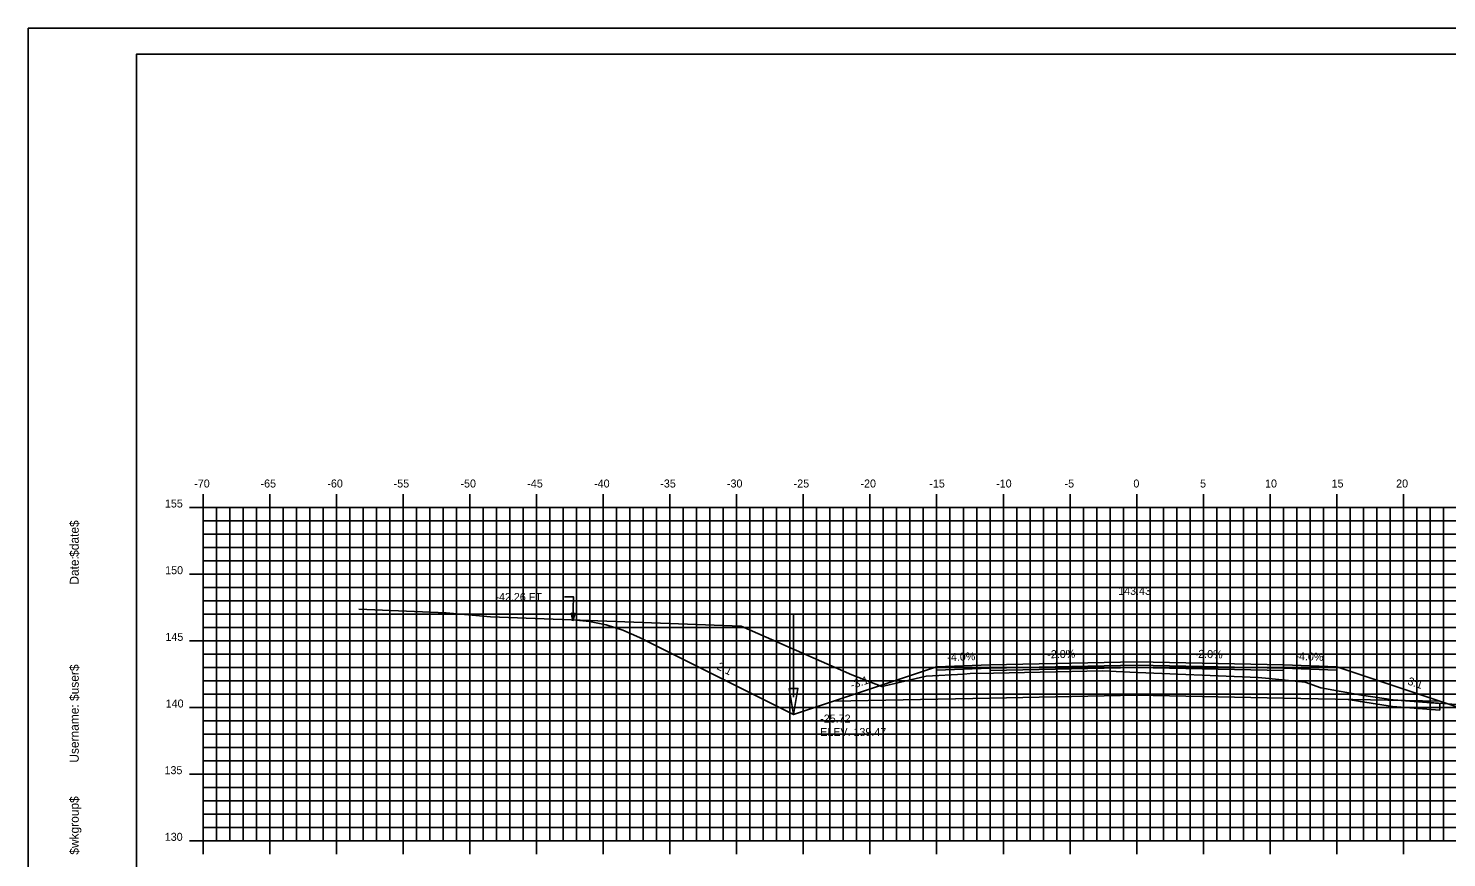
# Model space of a CAD drawing. Extents: x 1144307 to 1144477, y 608981 to 609091.
# Drawn here: x 1144307 to 1144413.3, y 609029.1 to 609091.3 of the extents above; entities that cross this region are included whole.
import ezdxf

# ---------------------------------------------------------------- set-up
doc = ezdxf.new("R2010")
doc.units = 0
for name, color, linetype in [('ANNOTATION', 7, 'Continuous'), ('BORDER', 7, 'Continuous'), ('D_Drainage_Ditch_Line', 7, 'Continuous'), ('D_Roadway_Centerline', 7, 'Continuous'), ('D_Roadway_Centerline_Text', 7, 'Continuous'), ('D_Roadway_Edge_Shoulder', 7, 'Continuous'), ('D_Roadway_Edge_TW', 7, 'Continuous'), ('D_Roadway_Pavement', 7, 'Continuous'), ('D_Roadway_SlopeLines', 7, 'Continuous'), ('D_Roadway_SubGrade', 7, 'Continuous'), ('D_Text_Standard', 7, 'Continuous'), ('H_V ANNOTATION', 7, 'Continuous'), ('MAJOR', 7, 'Continuous'), ('MINOR', 7, 'Continuous'), ('PLOT BOUNDARY', 7, 'Continuous'), ('S_Roadway_Centerline', 7, 'Continuous'), ('SHADING', 7, 'Continuous')]:
    doc.layers.add(name, color=color, linetype=linetype)

msp = doc.modelspace()

# ---------------------------------------------------------------- linework, layer by layer
msp.add_lwpolyline([(1144347.84, 609046.92), (1144349.09, 609046.8), (1144350.34, 609046.54), (1144351.59, 609046.13), (1144352.84, 609045.58), (1144364.38, 609039.81), (1144367.38, 609040.81), (1144375.1, 609043.38), (1144375.11, 609043.38), (1144379.11, 609043.54), (1144390.11, 609043.76), (1144401.11, 609043.54), (1144405.11, 609043.38), (1144412.83, 609040.81), (1144415.83, 609039.81), (1144416.37, 609040.04), (1144416.91, 609040.2), (1144417.45, 609040.29), (1144418, 609040.31)])
at = {"layer": 'BORDER'}
msp.add_lwpolyline([(1144315.11, 608984.34), (1144475.11, 608984.34), (1144475.11, 609089.34), (1144315.11, 609089.34)], close=True, dxfattribs=at)
at = {"layer": 'D_Drainage_Ditch_Line'}
msp.add_line((1144364.38, 609041.12), (1144364.38, 609047.36), dxfattribs=at)
msp.add_lwpolyline([(1144364.05, 609041.77), (1144364.71, 609041.77), (1144364.38, 609039.81)], close=True, dxfattribs=at)
at = {"layer": 'D_Roadway_Edge_Shoulder'}
for points in [[(1144379.11, 609043.54), (1144375.11, 609043.38), (1144375.11, 609043.13), (1144379.11, 609043.29)], [(1144401.11, 609043.54), (1144405.11, 609043.38), (1144405.11, 609043.13), (1144401.11, 609043.29)]]:
    msp.add_lwpolyline(points, close=True, dxfattribs=at)
at = {"layer": 'D_Roadway_Edge_TW'}
msp.add_lwpolyline([(1144379.11, 609043.29), (1144379.11, 609043.54), (1144390.11, 609043.76), (1144401.11, 609043.54), (1144401.11, 609043.29), (1144390.11, 609043.51)], close=True, dxfattribs=at)
at = {"layer": 'D_Roadway_Pavement'}
msp.add_lwpolyline([(1144379.11, 609043.12), (1144379.11, 609043.29), (1144390.11, 609043.51), (1144401.11, 609043.29), (1144401.11, 609043.12), (1144390.11, 609043.34)], close=True, dxfattribs=at)
at = {"layer": 'D_Roadway_SlopeLines'}
for points in [[(1144364.38, 609039.81), (1144352.84, 609045.58), (1144351.59, 609046.13), (1144350.34, 609046.54), (1144349.09, 609046.8), (1144347.84, 609046.92)], [(1144367.38, 609040.81), (1144364.38, 609039.81)], [(1144412.83, 609040.81), (1144415.83, 609039.81)]]:
    msp.add_lwpolyline(points, dxfattribs=at)
at = {"layer": 'D_Roadway_SubGrade'}
msp.add_line((1144412.83, 609040.65), (1144412.83, 609040.15), dxfattribs=at)
for points in [[(1144379.11, 609043.12), (1144379.11, 609043.29), (1144375.11, 609043.13), (1144375.11, 609043.38), (1144375.1, 609043.38), (1144367.38, 609040.81), (1144379.11, 609041.04)], [(1144379.11, 609041.04), (1144379.11, 609043.12), (1144390.11, 609043.34), (1144401.11, 609043.12), (1144401.11, 609041.04), (1144390.11, 609041.26)], [(1144401.11, 609043.12), (1144401.11, 609043.29), (1144405.11, 609043.13), (1144405.11, 609043.38), (1144405.11, 609043.38), (1144412.83, 609040.81), (1144401.11, 609041.04)]]:
    msp.add_lwpolyline(points, close=True, dxfattribs=at)
msp.add_lwpolyline([(1144405.96, 609040.94), (1144406.88, 609040.78), (1144409.28, 609040.41), (1144412.83, 609040.15)], dxfattribs=at)
at = {"layer": 'D_Text_Standard'}
msp.add_lwpolyline([(1144347.84, 609046.83), (1144347.89, 609048.63), (1144347.21, 609048.63)], dxfattribs=at)
msp.add_lwpolyline([(1144347.84, 609046.83), (1144347.71, 609047.41), (1144348, 609047.4)], close=True, dxfattribs=at)
at = {"layer": 'MAJOR'}
for p, q in [((1144320.11, 609056.34), (1144320.11, 609055.34)), ((1144325.11, 609056.34), (1144325.11, 609055.34)), ((1144330.11, 609056.34), (1144330.11, 609055.34)), ((1144335.11, 609056.34), (1144335.11, 609055.34)), ((1144340.11, 609056.34), (1144340.11, 609055.34)), ((1144345.11, 609056.34), (1144345.11, 609055.34)), ((1144350.11, 609056.34), (1144350.11, 609055.34)), ((1144355.11, 609056.34), (1144355.11, 609055.34)), ((1144360.11, 609056.34), (1144360.11, 609055.34)), ((1144365.11, 609056.34), (1144365.11, 609055.34)), ((1144370.11, 609056.34), (1144370.11, 609055.34)), ((1144375.11, 609056.34), (1144375.11, 609055.34)), ((1144380.11, 609056.34), (1144380.11, 609055.34)), ((1144385.11, 609056.34), (1144385.11, 609055.34)), ((1144390.11, 609056.34), (1144390.11, 609055.34)), ((1144395.11, 609056.34), (1144395.11, 609055.34)), ((1144400.11, 609056.34), (1144400.11, 609055.34)), ((1144405.11, 609056.34), (1144405.11, 609055.34)), ((1144410.11, 609056.34), (1144410.11, 609055.34)), ((1144319.1, 609055.34), (1144320.11, 609055.34)), ((1144320.11, 609055.34), (1144460.11, 609055.34)), ((1144320.11, 609030.34), (1144320.11, 609055.34)), ((1144320.11, 609030.34), (1144320.11, 609055.34)), ((1144320.11, 609055.34), (1144460.11, 609055.34)), ((1144325.11, 609030.34), (1144325.11, 609055.34)), ((1144330.11, 609030.34), (1144330.11, 609055.34)), ((1144335.11, 609030.34), (1144335.11, 609055.34)), ((1144340.11, 609030.34), (1144340.11, 609055.34)), ((1144345.11, 609030.34), (1144345.11, 609055.34)), ((1144350.11, 609030.34), (1144350.11, 609055.34)), ((1144355.11, 609030.34), (1144355.11, 609055.34)), ((1144360.11, 609030.34), (1144360.11, 609055.34)), ((1144365.11, 609030.34), (1144365.11, 609055.34)), ((1144370.11, 609030.34), (1144370.11, 609055.34)), ((1144375.11, 609030.34), (1144375.11, 609055.34)), ((1144380.11, 609030.34), (1144380.11, 609055.34)), ((1144385.11, 609030.34), (1144385.11, 609055.34)), ((1144390.11, 609030.34), (1144390.11, 609055.34)), ((1144395.11, 609030.34), (1144395.11, 609055.34)), ((1144400.11, 609030.34), (1144400.11, 609055.34)), ((1144405.11, 609030.34), (1144405.11, 609055.34)), ((1144410.11, 609030.34), (1144410.11, 609055.34)), ((1144319.1, 609050.34), (1144320.11, 609050.34)), ((1144320.11, 609050.34), (1144460.11, 609050.34)), ((1144319.1, 609045.34), (1144320.11, 609045.34)), ((1144320.11, 609045.34), (1144460.11, 609045.34)), ((1144319.1, 609040.34), (1144320.11, 609040.34)), ((1144320.11, 609040.34), (1144460.11, 609040.34)), ((1144319.1, 609035.34), (1144320.11, 609035.34)), ((1144320.11, 609035.34), (1144460.11, 609035.34)), ((1144319.1, 609030.34), (1144320.11, 609030.34)), ((1144320.11, 609030.34), (1144460.11, 609030.34)), ((1144320.11, 609030.34), (1144460.11, 609030.34)), ((1144320.11, 609029.33), (1144320.11, 609030.34)), ((1144325.11, 609029.33), (1144325.11, 609030.34)), ((1144330.11, 609029.33), (1144330.11, 609030.34)), ((1144335.11, 609029.33), (1144335.11, 609030.34)), ((1144340.11, 609029.33), (1144340.11, 609030.34)), ((1144345.11, 609029.33), (1144345.11, 609030.34)), ((1144350.11, 609029.33), (1144350.11, 609030.34)), ((1144355.11, 609029.33), (1144355.11, 609030.34)), ((1144360.11, 609029.33), (1144360.11, 609030.34)), ((1144365.11, 609029.33), (1144365.11, 609030.34)), ((1144370.11, 609029.33), (1144370.11, 609030.34)), ((1144375.11, 609029.33), (1144375.11, 609030.34)), ((1144380.11, 609029.33), (1144380.11, 609030.34)), ((1144385.11, 609029.33), (1144385.11, 609030.34)), ((1144390.11, 609029.33), (1144390.11, 609030.34)), ((1144395.11, 609029.33), (1144395.11, 609030.34)), ((1144400.11, 609029.33), (1144400.11, 609030.34)), ((1144405.11, 609029.33), (1144405.11, 609030.34)), ((1144410.11, 609029.33), (1144410.11, 609030.34))]:
    msp.add_line(p, q, dxfattribs=at)
at = {"layer": 'MINOR'}
for p, q in [((1144321.11, 609030.34), (1144321.11, 609055.34)), ((1144322.11, 609030.34), (1144322.11, 609055.34)), ((1144323.11, 609030.34), (1144323.11, 609055.34)), ((1144324.11, 609030.34), (1144324.11, 609055.34)), ((1144326.11, 609030.34), (1144326.11, 609055.34)), ((1144327.11, 609030.34), (1144327.11, 609055.34)), ((1144328.11, 609030.34), (1144328.11, 609055.34)), ((1144329.11, 609030.34), (1144329.11, 609055.34)), ((1144331.11, 609030.34), (1144331.11, 609055.34)), ((1144332.11, 609030.34), (1144332.11, 609055.34)), ((1144333.11, 609030.34), (1144333.11, 609055.34)), ((1144334.11, 609030.34), (1144334.11, 609055.34)), ((1144336.11, 609030.34), (1144336.11, 609055.34)), ((1144337.11, 609030.34), (1144337.11, 609055.34)), ((1144338.11, 609030.34), (1144338.11, 609055.34)), ((1144339.11, 609030.34), (1144339.11, 609055.34)), ((1144341.11, 609030.34), (1144341.11, 609055.34)), ((1144342.11, 609030.34), (1144342.11, 609055.34)), ((1144343.11, 609030.34), (1144343.11, 609055.34)), ((1144344.11, 609030.34), (1144344.11, 609055.34)), ((1144346.11, 609030.34), (1144346.11, 609055.34)), ((1144347.11, 609030.34), (1144347.11, 609055.34)), ((1144348.11, 609030.34), (1144348.11, 609055.34)), ((1144349.11, 609030.34), (1144349.11, 609055.34)), ((1144351.11, 609030.34), (1144351.11, 609055.34)), ((1144352.11, 609030.34), (1144352.11, 609055.34)), ((1144353.11, 609030.34), (1144353.11, 609055.34)), ((1144354.11, 609030.34), (1144354.11, 609055.34)), ((1144356.11, 609030.34), (1144356.11, 609055.34)), ((1144357.11, 609030.34), (1144357.11, 609055.34)), ((1144358.11, 609030.34), (1144358.11, 609055.34)), ((1144359.11, 609030.34), (1144359.11, 609055.34)), ((1144361.11, 609030.34), (1144361.11, 609055.34)), ((1144362.11, 609030.34), (1144362.11, 609055.34)), ((1144363.11, 609030.34), (1144363.11, 609055.34)), ((1144364.11, 609030.34), (1144364.11, 609055.34)), ((1144366.11, 609030.34), (1144366.11, 609055.34)), ((1144367.11, 609030.34), (1144367.11, 609055.34)), ((1144368.11, 609030.34), (1144368.11, 609055.34)), ((1144369.11, 609030.34), (1144369.11, 609055.34)), ((1144371.11, 609030.34), (1144371.11, 609055.34)), ((1144372.11, 609030.34), (1144372.11, 609055.34)), ((1144373.11, 609030.34), (1144373.11, 609055.34)), ((1144374.11, 609030.34), (1144374.11, 609055.34)), ((1144376.11, 609030.34), (1144376.11, 609055.34)), ((1144377.11, 609030.34), (1144377.11, 609055.34)), ((1144378.11, 609030.34), (1144378.11, 609055.34)), ((1144379.11, 609030.34), (1144379.11, 609055.34)), ((1144381.11, 609030.34), (1144381.11, 609055.34)), ((1144382.11, 609030.34), (1144382.11, 609055.34)), ((1144383.11, 609030.34), (1144383.11, 609055.34)), ((1144384.11, 609030.34), (1144384.11, 609055.34)), ((1144386.11, 609030.34), (1144386.11, 609055.34)), ((1144387.11, 609030.34), (1144387.11, 609055.34)), ((1144388.11, 609030.34), (1144388.11, 609055.34)), ((1144389.11, 609030.34), (1144389.11, 609055.34)), ((1144391.11, 609030.34), (1144391.11, 609055.34)), ((1144392.11, 609030.34), (1144392.11, 609055.34)), ((1144393.11, 609030.34), (1144393.11, 609055.34)), ((1144394.11, 609030.34), (1144394.11, 609055.34)), ((1144396.11, 609030.34), (1144396.11, 609055.34)), ((1144397.11, 609030.34), (1144397.11, 609055.34)), ((1144398.11, 609030.34), (1144398.11, 609055.34)), ((1144399.11, 609030.34), (1144399.11, 609055.34)), ((1144401.11, 609030.34), (1144401.11, 609055.34)), ((1144402.11, 609030.34), (1144402.11, 609055.34)), ((1144403.11, 609030.34), (1144403.11, 609055.34)), ((1144404.11, 609030.34), (1144404.11, 609055.34)), ((1144406.11, 609030.34), (1144406.11, 609055.34)), ((1144407.11, 609030.34), (1144407.11, 609055.34)), ((1144408.11, 609030.34), (1144408.11, 609055.34)), ((1144409.11, 609030.34), (1144409.11, 609055.34)), ((1144411.11, 609030.34), (1144411.11, 609055.34)), ((1144412.11, 609030.34), (1144412.11, 609055.34)), ((1144413.11, 609030.34), (1144413.11, 609055.34)), ((1144320.11, 609054.34), (1144460.11, 609054.34)), ((1144320.11, 609054.34), (1144321.11, 609054.34)), ((1144320.11, 609053.34), (1144460.11, 609053.34)), ((1144320.11, 609053.34), (1144321.11, 609053.34)), ((1144320.11, 609052.34), (1144460.11, 609052.34)), ((1144320.11, 609052.34), (1144321.11, 609052.34)), ((1144320.11, 609051.34), (1144460.11, 609051.34)), ((1144320.11, 609051.34), (1144321.11, 609051.34)), ((1144320.11, 609049.34), (1144460.11, 609049.34)), ((1144320.11, 609049.34), (1144321.11, 609049.34)), ((1144320.11, 609048.34), (1144460.11, 609048.34)), ((1144320.11, 609048.34), (1144321.11, 609048.34)), ((1144320.11, 609047.34), (1144460.11, 609047.34)), ((1144320.11, 609047.34), (1144321.11, 609047.34)), ((1144320.11, 609046.34), (1144460.11, 609046.34)), ((1144320.11, 609046.34), (1144321.11, 609046.34)), ((1144320.11, 609044.34), (1144460.11, 609044.34)), ((1144320.11, 609044.34), (1144321.11, 609044.34)), ((1144320.11, 609043.34), (1144460.11, 609043.34)), ((1144320.11, 609043.34), (1144321.11, 609043.34)), ((1144320.11, 609042.34), (1144460.11, 609042.34)), ((1144320.11, 609042.34), (1144321.11, 609042.34)), ((1144320.11, 609041.34), (1144460.11, 609041.34)), ((1144320.11, 609041.34), (1144321.11, 609041.34)), ((1144320.11, 609039.34), (1144460.11, 609039.34)), ((1144320.11, 609039.34), (1144321.11, 609039.34)), ((1144320.11, 609038.34), (1144460.11, 609038.34)), ((1144320.11, 609038.34), (1144321.11, 609038.34)), ((1144320.11, 609037.34), (1144460.11, 609037.34)), ((1144320.11, 609037.34), (1144321.11, 609037.34)), ((1144320.11, 609036.34), (1144460.11, 609036.34)), ((1144320.11, 609036.34), (1144321.11, 609036.34)), ((1144320.11, 609034.34), (1144460.11, 609034.34)), ((1144320.11, 609034.34), (1144321.11, 609034.34)), ((1144320.11, 609033.34), (1144460.11, 609033.34)), ((1144320.11, 609033.34), (1144321.11, 609033.34)), ((1144320.11, 609032.34), (1144460.11, 609032.34)), ((1144320.11, 609032.34), (1144321.11, 609032.34)), ((1144320.11, 609031.34), (1144460.11, 609031.34)), ((1144320.11, 609031.34), (1144321.11, 609031.34))]:
    msp.add_line(p, q, dxfattribs=at)
at = {"layer": 'PLOT BOUNDARY'}
msp.add_lwpolyline([(1144307.01, 608981.28), (1144477.01, 608981.28), (1144477.01, 609091.28), (1144307.01, 609091.28)], close=True, dxfattribs=at)
at = {"layer": 'S_Roadway_Centerline'}
msp.add_lwpolyline([(1144331.78, 609047.72), (1144338.33, 609047.45), (1144341.66, 609047.15), (1144360.45, 609046.45), (1144368.74, 609042.79), (1144371, 609041.91), (1144371.56, 609042.05), (1144374.33, 609042.69), (1144377.15, 609042.85), (1144377.61, 609042.88), (1144379.36, 609042.91), (1144387.54, 609043.08), (1144389.6, 609042.98), (1144399.22, 609042.59), (1144399.77, 609042.53), (1144402.74, 609042.24), (1144403.91, 609041.82), (1144406.96, 609041.27), (1144409.33, 609040.91), (1144417.14, 609040.33), (1144429.03, 609040), (1144436.35, 609039.58), (1144453.35, 609038.07), (1144457.82, 609038.12)], dxfattribs=at)
at = {"layer": 'SHADING'}
for p, q in [((1144412.83, 609040.65), (1144409.94, 609040.86)), ((1144412.83, 609040.15), (1144412.83, 609040.65))]:
    msp.add_line(p, q, dxfattribs=at)
for points in [[(1144405.96, 609040.94), (1144406.88, 609040.78), (1144409.28, 609040.41), (1144412.83, 609040.15)], [(1144409.94, 609040.86), (1144409.33, 609040.88), (1144405.96, 609040.94)]]:
    msp.add_lwpolyline(points, dxfattribs=at)

# ---------------------------------------------------------------- texts
at = {"layer": 'ANNOTATION'}
for s, rotation, p in [('-4.0%', 2.2906, (1144375.92, 609043.81)), ('-2.0%', 1.1458, (1144383.41, 609044.03)), ('-2.0%', 358.8542, (1144394.45, 609044.07)), ('-4.0%', 357.7094, (1144402, 609043.91)), ('2:1', 333.4349, (1144358.58, 609043.23)), ('-3:1', 18.4348, (1144368.76, 609041.72)), ('-3:1', 341.5652, (1144410.12, 609042.16))]:
    msp.add_text(s, height=0.6, rotation=rotation, dxfattribs=at).set_placement(p)
at = {"layer": 'BORDER'}
for s, p in [('$date$', (1144310.79, 609051.64)), ('Date:', (1144310.79, 609049.55)), ('$user$', (1144310.79, 609040.83)), ('Username:', (1144310.79, 609036.2)), ('$wkgroup$', (1144310.79, 609029.3))]:
    msp.add_text(s, height=0.67, rotation=90, dxfattribs=at).set_placement(p)
at = {"layer": 'D_Roadway_Centerline'}
for s, p in [('C', (1144390.1, 609043.76)), ('L', (1144390.11, 609043.75))]:
    msp.add_text(s, height=0.0146, dxfattribs=at).set_placement(p)
at = {"layer": 'D_Roadway_Centerline_Text'}
msp.add_text('143.43', height=0.6, dxfattribs=at).set_placement((1144388.72, 609048.79))
at = {"layer": 'D_Text_Standard'}
for s, p in [('-42.26 FT', (1144342.03, 609048.33)), ('-25.72', (1144366.38, 609039.21)), ('ELEV. 139.47', (1144366.38, 609038.2))]:
    msp.add_text(s, height=0.6, dxfattribs=at).set_placement(p)
at = {"layer": 'H_V ANNOTATION'}
for s, p in [('-70', (1144319.45, 609056.84)), ('-65', (1144324.42, 609056.84)), ('-60', (1144329.43, 609056.84)), ('-55', (1144334.4, 609056.84)), ('-50', (1144339.41, 609056.84)), ('-45', (1144344.42, 609056.84)), ('-40', (1144349.43, 609056.84)), ('-35', (1144354.39, 609056.84)), ('-30', (1144359.39, 609056.84)), ('-25', (1144364.39, 609056.84)), ('-20', (1144369.4, 609056.84)), ('-15', (1144374.56, 609056.84)), ('-10', (1144379.57, 609056.84)), ('-5', (1144384.7, 609056.84)), ('0', (1144389.86, 609056.84)), ('5', (1144394.86, 609056.84)), ('10', (1144399.73, 609056.84)), ('15', (1144404.72, 609056.84)), ('20', (1144409.56, 609056.84)), ('155', (1144317.25, 609055.34)), ('150', (1144317.27, 609050.34)), ('145', (1144317.29, 609045.34)), ('140', (1144317.31, 609040.34)), ('135', (1144317.22, 609035.34)), ('130', (1144317.24, 609030.34))]:
    msp.add_text(s, height=0.6, dxfattribs=at).set_placement(p)
at = {"layer": 'MAJOR'}
msp.add_text('-', height=0.006, dxfattribs=at).set_placement((1144320.1, 609030.34))
at = {"layer": 'S_Roadway_Centerline'}
for s, p in [('C', (1144387.53, 609043.08)), ('L', (1144387.53, 609043.07))]:
    msp.add_text(s, height=0.0146, dxfattribs=at).set_placement(p)

doc.saveas('drawing.dxf')
